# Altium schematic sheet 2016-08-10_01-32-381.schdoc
size 288 x 149 mm; SheetNumber: 1; SheetTotal: 1
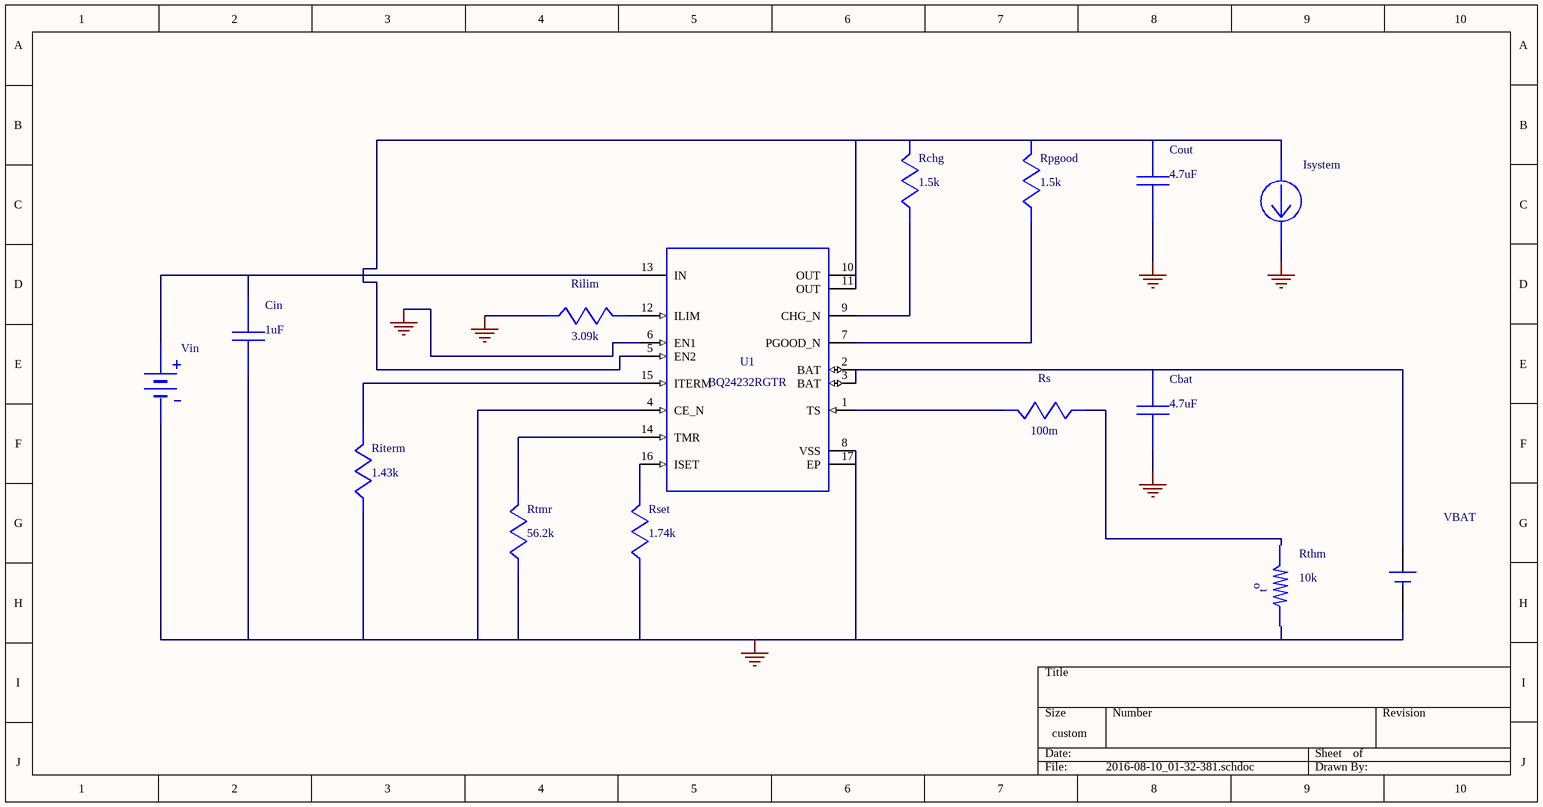
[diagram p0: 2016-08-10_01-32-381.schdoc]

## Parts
Cbat  value 4.7uF  (hidden comment: GRM21BR61E475KA12L)
Cin  value 1uF  (hidden comment: GRM188R61A105KA61D)
Cout  value 4.7uF  (hidden comment: GRM21BR61A475KA73L)
Isystem  WB_CURRENT_LOAD  (value not drawn)
Rchg  value 1.5k  (hidden comment: CRCW04021K50FKED)
Rilim  value 3.09k  (hidden comment: CRCW04023K09FKED)
Riterm  value 1.43k  (hidden comment: CRCW04021K43FKED)
Rpgood  value 1.5k  (hidden comment: CRCW04021K50FKED)
Rs  value 100m  (hidden comment: ERJ-3RSFR10V)
Rset  value 1.74k  (hidden comment: CRCW04021K74FKED)
Rthm  value 10k  (hidden comment: NCP15XH103E03RC)
Rtmr  value 56.2k  (hidden comment: CRCW040256K2FKED)
U1  BQ24232RGTR
VBAT  WB_BATTERY_SINGLE_USFP  (value not drawn)
Vin  WB_BATTERY  (value not drawn)

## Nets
0: Cbat.2 Cin.2 Cout.2 Isystem.2(-) Rilim.2 Riterm.2 Rset.2 Rtmr.2 U1.4(CE_N) U1.6(EN1) U1.8(VSS) U1.17(EP) VBAT.2(-) Vin.2(-)
NetCbat_1: Cbat.1 U1.2(BAT) U1.3(BAT) VBAT.1(+)
NetCin_1: Cin.1 U1.13(IN) Vin.1(+)
NetCout_1: Cout.1 Isystem.1(+) Rchg.1 Rpgood.1 U1.5(EN2) U1.10(OUT) U1.11(OUT)
NetRchg_2: Rchg.2 U1.9(CHG_N)
NetRilim_1: Rilim.1 U1.12(ILIM)
NetRiterm_1: Riterm.1 U1.15(ITERM)
NetRpgood_2: Rpgood.2 U1.7(PGOOD_N)
NetRs_1: Rs.1 U1.1(TS)
NetRset_1: Rset.1 U1.16(ISET)
NetRtmr_1: Rtmr.1 U1.14(TMR)

Not connected (* = marked no-connect by the designer): Rs 2; Rthm 1 2

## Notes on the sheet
- (near Rthm) o
- (near Rthm) t

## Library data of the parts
Cbat = GRM21BR61E475KA12L: GRM21BR61E475KA1; Manufacturer Name: MuRata
Cin = GRM188R61A105KA61D: GRM188R61A105KA6; Manufacturer Name: MuRata
Cout = GRM21BR61A475KA73L: GRM21BR61A475KA7; Manufacturer Name: MuRata
Rchg Rpgood = CRCW04021K50FKED: Manufacturer Name: Vishay-Dale
Rilim = CRCW04023K09FKED: Manufacturer Name: Vishay-Dale
Riterm = CRCW04021K43FKED: Manufacturer Name: Vishay-Dale
Rs = ERJ-3RSFR10V: Manufacturer Name: Panasonic
Rset = CRCW04021K74FKED: Manufacturer Name: Vishay-Dale
Rthm = NCP15XH103E03RC: Manufacturer Name: MuRata
Rtmr = CRCW040256K2FKED: Manufacturer Name: Vishay-Dale
U1 = BQ24232RGTR: Manufacturer Name: Texas Instruments
VBAT = WB_BATTERY_SINGLE_USFP: WB_BATTERY_SINGL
